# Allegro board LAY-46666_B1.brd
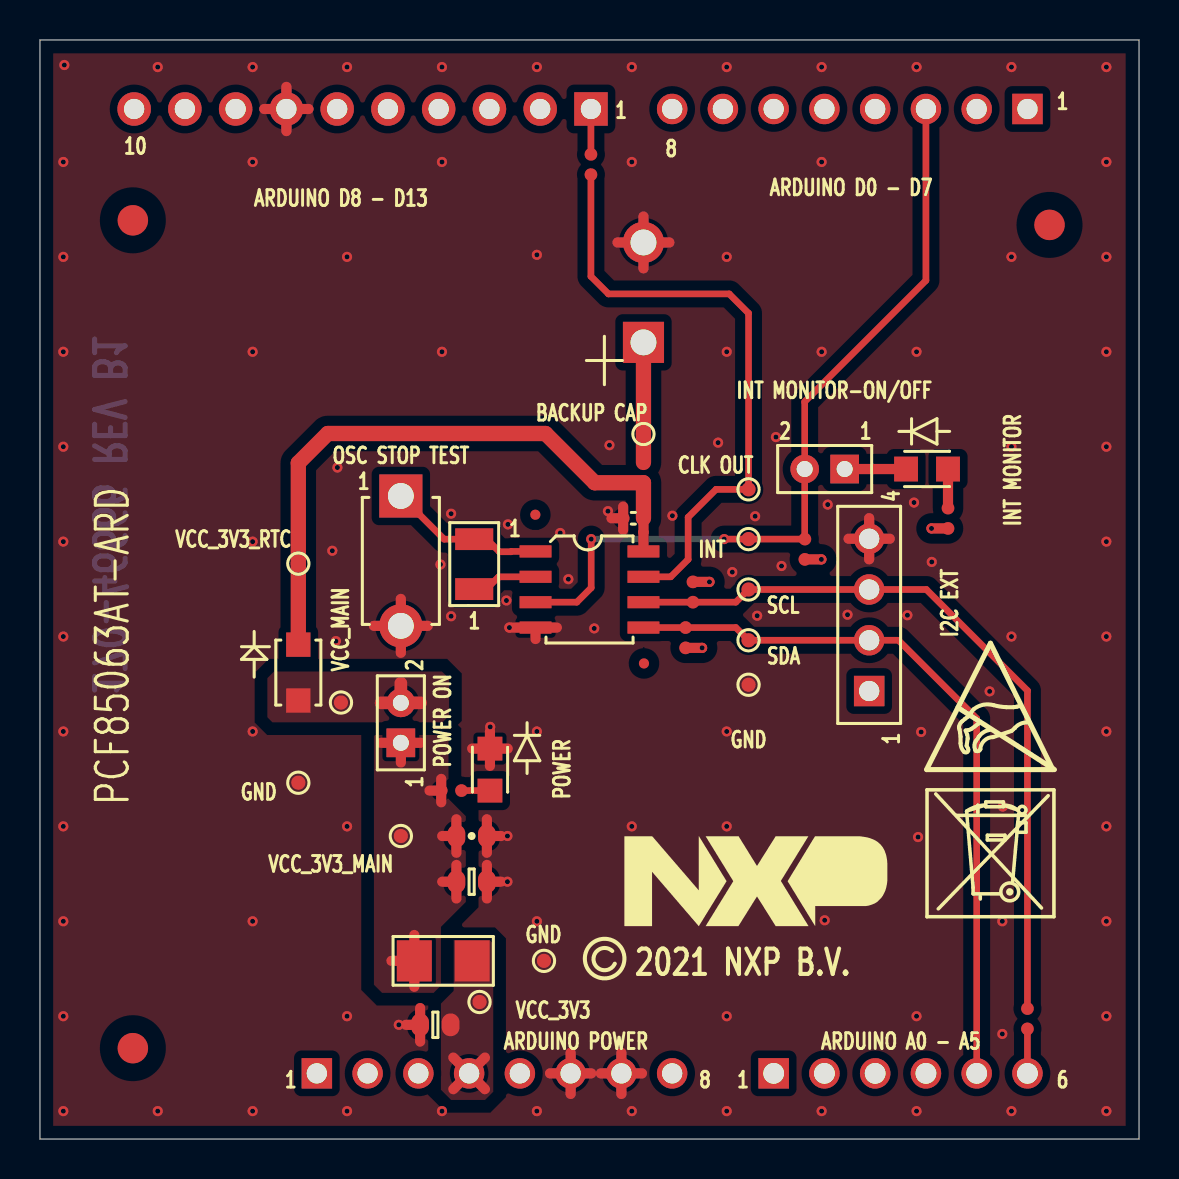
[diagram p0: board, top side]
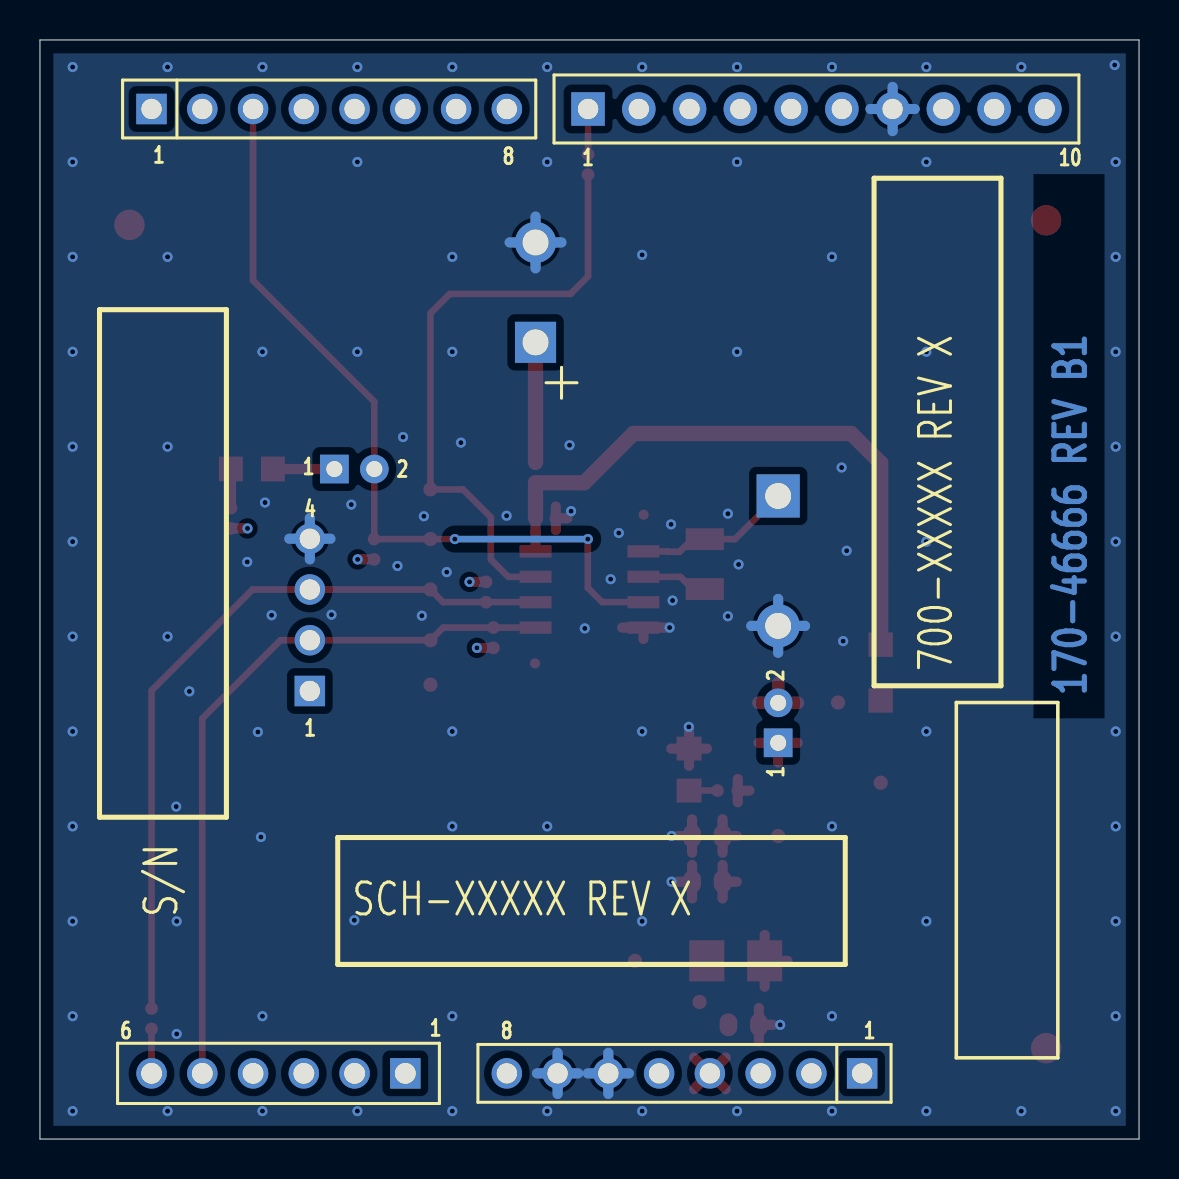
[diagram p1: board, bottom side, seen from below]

Outline 55 x 55 mm; copper layers: TOP, L2_GND, L3_PWR, BOTTOM. Coordinates in mm from the lower left corner of the outline.
Outline path: 0,55 0,0 55,0 55,55 0,55

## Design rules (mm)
constraint set DEFAULT: min track width 0.33
net group POWER: nets VCC_3V3_RTC

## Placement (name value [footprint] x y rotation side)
C1  10uF  [CC0603_OV]  19.79 5.71 180 top
C3  10uF  [CC0603_OV]  21.6 12.88 0 top
C7  0.1uF  [CC0402_25]  29.69 31.06 180 top
C8  1F  [CAP_5X19P2_TH]  30.2 42.37 270 top
D1  RED  [LED_2P_0805]  22.52 18.49 270 top
D2  RED  [LED_2P_0805]  44.39 33.53 0 top
D3  BAT54H,115  [SOD123W]  12.93 23.34 270 top
J1  HDR 1X6  [HDR106_TH_TSW]  36.72 3.29 270 bottom
J4  TSW-110-07-T-S  [HDR110]  27.57 51.55 90 bottom
J5  TSW-108-07-T-S  [JUMP1X8-6040]  49.42 51.55 90 bottom
J6  TSW-108-07-T-S  [JUMP1X8-6040]  13.86 3.29 270 bottom
J24  HDR 1x2 TH  [HDR102_78MIL_TH]  40.27 33.53 0 top
J37  HDR 1x2 TH  [HDR102_78MIL_TH]  18.06 19.83 270 top
J38  HDR_1X4  [HDR104_2P54_TH]  41.49 22.42 180 top
L2  100 OHM  [IND_1206A]  20.18 8.92 180 top
NOREF  -  []  25.81 28.43 90 top
NOREF#2  -  [unnamed#2]  30.23 23.8 0 top
NOREF#3  -  []  13.88 20.04 90 top
NOREF#4  -  []  29.26 10.66 0 top
NOREF#5  -  []  0 0 0 top
NOREF#6  -  []  42.89 10.46 0 top
NOREF#7  -  [unnamed#2]  4.65 4.55 0 top
NOREF#8  -  []  30.2 39.87 90 top
NOREF#9  -  []  28.26 9 0 top
NOREF#10  -  []  71.58 -68.17 0 top
NOREF#11  -  []  19.81 28.43 0 top
NOREF#12  -  []  38.27 33.53 0 top
NOREF#13  -  []  -313.23 -292.32 0 top
NOREF#14  -  []  41.49 22.42 90 top
NOREF#15  -  []  -286.56 228.76 0 top
NOREF#16  -  []  20.6 44.87 0 top
NOREF#17  -  []  45.68 10.46 90 top
NOREF#18  -  []  17.06 23 0 top
NOREF#19  -  []  44.39 18.49 0 top
NOREF#20  -  []  41.49 22.42 90 top
NOREF#21  -  [unnamed#2]  50.52 45.75 0 top
NOREF#22  -  []  0 0 0 top
NOREF#23  -  []  0 55 0 top
NOREF#24  -  []  44.39 11.13 0 top
NOREF#25  -  [unnamed#2]  4.65 45.97 0 top
NOREF#26  -  []  18.06 25.68 90 top
NOREF#27  -  []  55 0 90 top
NOREF#28  -  []  25.03 51.55 0 top
NOREF#29  -  []  11.08 20.04 0 top
NOREF#30  -  []  18.06 19.83 90 top
NOREF#31  -  []  2.16 10.67 0 top
NOREF#32  -  []  21.41 23 90 top
NOREF#33  -  []  0 0 0 top
NOREF#34  -  []  25.6 44.87 90 top
NOREF#35  -  []  41.44 32.53 90 top
NOREF#36  -  []  37.09 32.53 0 top
NOREF#37  -  [unnamed#2]  24.79 31.24 180 top
NOREF#38  -  []  45.67 16.1 90 bottom
NOREF#39  -  []  6.91 22.68 90 bottom
NOREF#40  -  []  40.1 8.74 180 bottom
NOREF#41  -  []  9.14 21.84 270 bottom
R1  330 OHM  [RC0402_25]  20.59 17.44 0 top
R2  5.6K  [RC0402_25]  38.28 29.51 90 top
R3  AVR-M1608C080MTAAB  [RC0603_OV]  21.6 15.16 0 top
R29  750  [RC0402_25]  45.44 31.06 90 top
R30  5.6K  [RC0402_25]  32.68 27.37 270 top
R31  5.6K  [RC0402_25]  32.31 25.09 90 top
R32  47  [RC0402_25]  30.2 33.35 270 top
R35  0  [RC0402_25]  27.57 48.77 90 top
R36  0  [RC0402_25]  49.42 6.02 270 top
SW1  TL1107  [SW2_6P5_6X3MM_TH]  18.06 32.18 270 top
TP1  -  [TPAD_028]  35.46 32.51 0 top
TP2  -  [TPAD_028]  35.46 30.02 0 top
TP3  -  [TPAD_028]  35.46 24.96 0 top
TP4  -  [TPAD_028]  35.46 27.5 0 top
TP5  -  [TPAD_028]  22 6.86 0 top
TP6  -  [TPAD_028]  30.2 35.28 0 top
TP7  -  [TPAD_028]  18.06 15.16 0 top
TP8  -  [TPAD_028]  12.93 28.8 0 top
TP9  -  [TPAD_028]  25.22 8.92 0 top
TP10  -  [TPAD_028]  12.93 17.83 0 top
TP11  -  [TPAD_028]  15.06 21.84 0 top
TP12  -  [TPAD_028]  35.46 22.73 0 top
U1  PCF85063AT/A  [SO8_1P27_4X5]  27.5 27.5 0 top
Y1  32.768kHz  [XTAL2-3P2X1P5-SM]  21.73 28.77 90 top

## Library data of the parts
C1 C3 C7 = CAP_NP
C8 = CAP_POL
D1 D2 = LED
D3 = DIODE_SCHTKY
J1 = CONN_HDR_6X1
J4 = CONN_HDR_10X1
J5 J6 = HDR-1X8
J24 J37 = HDR_1X2_TH
J38 = CONN_HDR_4X1
L2 = IND_BF: tolerance: XXXX
R1 R2 R29-R32 R35 R36 = RES
R3 = VARISTOR
SW1 = SW2P
TP1-TP12 = TESTLOOP
U1 = PCF85063ATT_A
Y1 = XTAL

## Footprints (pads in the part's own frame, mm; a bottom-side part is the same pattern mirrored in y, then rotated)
CAP_5X19P2_TH
  rect 2.057x2.057 hole 1.295: 1(2.5,0)
  round 2.057 hole 1.295: 2(-2.5,0)
CC0402_25
  round 0.635 smd: 1(-0.508,0) 2(0.508,0)
CC0603_OV
  oval 0.889x1.143 smd: 1(-0.762,0) 2(0.762,0)
HDR102_78MIL_TH
  rect 1.435x1.435 hole 0.8: 1(0,0)
  round 1.435 hole 0.8: 2(-2,0)
HDR104_2P54_TH
  rect 1.524x1.524 hole 1.016: 1(0,0)
  round 1.524 hole 1.016: 2(0,-2.54) 3(0,-5.08) 4(0,-7.62)
HDR106_TH_TSW
  rect 1.524x1.524 hole 1.041: 1(0,0)
  round 1.524 hole 1.041: 2(0,-2.54) 3(0,-5.08) 4(0,-7.62) 5(0,-10.16) 6(0,-12.7)
HDR110
  rect 1.676x1.676 hole 1.016: 1(0,0)
  round 1.676 hole 1.016: 2(0,-2.54) 3(0,-5.08) 4(0,-7.62) 5(0,-10.16) 6(0,-12.7) 7(0,-15.24) 8(0,-17.78) 9(0,-20.32) 10(0,-22.86)
IND_1206A
  rect 1.753x2.057 smd: 1(-1.448,0) 2(1.448,0)
JUMP1X8-6040
  rect 1.524x1.524 hole 1.016: 1(0,0)
  round 1.524 hole 1.016: 2(0,-2.54) 3(0,-5.08) 4(0,-7.62) 5(0,-10.16) 6(0,-12.7) 7(0,-15.24) 8(0,-17.78)
LED_2P_0805
  rect 1.194x1.245 smd: A(1.05,0) C(-1.05,0)
RC0402_25
  round 0.635 smd: 1(-0.508,0) 2(0.508,0)
RC0603_OV
  oval 0.889x1.143 smd: 1(-0.762,0) 2(0.762,0)
SO8_1P27_4X5
  rect 1.6x0.61 smd: 1(-2.7,1.905) 2(-2.7,0.635) 3(-2.7,-0.635) 4(-2.7,-1.905) 5(2.7,-1.905) 6(2.7,-0.635) 7(2.7,0.635) 8(2.7,1.905)
SOD123W
  rect 1.219x1.219 smd: A(1.4,0) C(-1.4,0)
SW2_6P5_6X3MM_TH
  rect 2.159x2.159 hole 1.295: 1(0,0)
  round 2.159 hole 1.295: 2(6.5,0)
TPAD_028
  round 0.711 smd: 1(0,0)
unnamed#2
  round 0.508 smd: (0,0)
XTAL2-3P2X1P5-SM
  rect 1.092x1.905 smd: 1(-1.25,0) 2(1.25,0)

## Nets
GND: C1.2 C3.2 C7.2 C8.2 D1.C(CATHODE) J4.7 J6.6 J6.7 J38.4 R3.2 SW1.2(NO) TP9.1(PIN1) TP10.1(PIN1) TP12.1(PIN1) U1.4(VSS)
VCC_3V3: C1.1 J6.4 J38.1 L2.1 TP5.1(PIN1)
VCC_3V3_MAIN: C3.1 J37.1 L2.2 R1.1 R3.1 TP7.1(PIN1)
VCC_3V3_RTC: C7.1 D3.C R32.2 TP8.1(PIN1) U1.8
VCC_MAIN: D3.A J37.2 R2.1 R29.1 R30.1 R31.1 TP11.1(PIN1)
CLK_OUT: J4.1 R35.2
I2C_3V3_SCL: J38.3 R30.2 R36.1 TP4.1(PIN1) U1.6
I2C_3V3_SDA: J1.5 J38.2 R31.2 TP3.1(PIN1) U1.5
I2C_SCL: J1.6 R36.2
INT_LED: D2.A R29.2
LED_3V3: D1.A R1.2
OSCI: SW1.1 U1.1 Y1.2
OSCO: U1.2 Y1.1
RTC_CLKOUT: R35.1 TP1.1(PIN1) U1.7
RTC_INT_B: J5.3 J24.2 R2.2 TP2.1(PIN1) U1.3
RTC_LED: D2.C(CATHODE) J24.1
SPR_CAP: C8.1 R32.1 TP6.1(PIN1)

Pads without a net: J1 1 2 3 4; J4 2 3 4 5 6 8 9 10; J5 1 2 4 5 6 7 8; J6 1 2 3 5 8

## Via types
v1: diameter 0.508, hole 0.254, TOP to BOTTOM, 114 vias

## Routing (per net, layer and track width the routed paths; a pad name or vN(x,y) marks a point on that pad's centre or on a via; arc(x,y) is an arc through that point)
GND: length 112.2
  TOP w0.508: J38.4 42.52,30.04 ; J38.4 41.49,29.01 ; J38.4 41.49,31.07 ; J38.4 40.47,30.04 ; 22.36,12.04 C3.2 ; C3.2 23.08,12.88 ; C3.2 22.36,13.72 ; J6.6 26.56,4.32 ; J6.6 27.59,3.29 ; J6.6 25.53,3.29 ; J6.6 26.56,2.26 ; C7.2 29.18,31.65 ; C7.2 29.18,30.48 ; C7.2 28.6,31.06 ; C8.2 31.5,44.87 ; C8.2 28.9,44.87 ; C8.2 30.2,46.16 ; C8.2 30.2,43.57 ; J6.7 29.1,4.32 ; J6.7 28.07,3.29 ; J6.7 29.1,2.26 ; J6.7 30.13,3.29 ; SW1.2 18.06,27.03 ; SW1.2 19.41,25.68 ; SW1.2 18.06,24.33 ; SW1.2 16.71,25.68 ; 21.63,19.54 D1.C ; D1.C 23.41,19.54 ; D1.C 22.52,20.4 ; D1.C 22.52,18.67 ; R3.2 23.08,15.16 ; R3.2 22.36,14.33 ; R3.2 22.36,16 ; U1.4 v1(23.49,25.59) ; U1.4 25.87,25.59 ; U1.4 24.8,25.02 ; 11.23,51.55 J4.7 ; J4.7 12.33,50.44 ; J4.7 12.33,52.65 ; J4.7 13.44,51.55 ; 18.31,5.71 C1.2 ; C1.2 19.02,6.55 ; C1.2 19.02,4.88
  L2_GND w0.508: 18.06,24.41 SW1.2 ; SW1.2 16.79,25.68 ; SW1.2 19.33,25.68 ; SW1.2 18.06,26.95 ; 29.1,2.33 J6.7 ; J6.7 29.1,4.24 ; J6.7 28.14,3.29 ; J6.7 30.05,3.29 ; J4.7 13.36,51.55 ; J4.7 11.3,51.55 ; J4.7 12.33,52.58 ; J4.7 12.33,50.52 ; J6.6 27.51,3.29 ; J6.6 26.56,4.24 ; J6.6 25.6,3.29 ; J6.6 26.56,2.33 ; 40.54,30.04 J38.4 ; J38.4 41.49,30.99 ; J38.4 42.45,30.04 ; J38.4 41.49,29.09 ; C8.2 30.2,46.09 ; C8.2 28.98,44.87 ; C8.2 31.42,44.87 ; C8.2 30.2,43.65
  L3_PWR w0.508: J4.7 12.33,52.58 ; J4.7 11.3,51.55 ; J4.7 13.36,51.55 ; J4.7 12.33,50.52 ; 29.1,2.33 J6.7 ; J6.7 28.14,3.29 ; J6.7 30.05,3.29 ; J6.7 29.1,4.24 ; 25.6,3.29 J6.6 ; J6.6 26.56,4.24 ; J6.6 26.56,2.33 ; J6.6 27.51,3.29 ; C8.2 31.42,44.87 ; C8.2 30.2,43.65 ; C8.2 28.98,44.87 ; C8.2 30.2,46.09
  BOTTOM w0.508: 18.06,24.33 SW1.2 ; SW1.2 16.71,25.68 ; SW1.2 19.41,25.68 ; SW1.2 18.06,27.03 ; J6.7 30.13,3.29 ; J6.7 29.1,2.26 ; J6.7 29.1,4.32 ; J6.7 28.07,3.29 ; 26.56,2.26 J6.6 ; J6.6 27.59,3.29 ; J6.6 26.56,4.32 ; J6.6 25.53,3.29 ; 40.47,30.04 J38.4 ; J38.4 42.52,30.04 ; J38.4 41.49,31.07 ; J38.4 41.49,29.01 ; 11.23,51.55 J4.7 ; J4.7 12.33,50.44 ; J4.7 12.33,52.65 ; J4.7 13.44,51.55 ; 28.9,44.87 C8.2 ; C8.2 30.2,46.16 ; C8.2 30.2,43.57 ; C8.2 31.5,44.87
  vias: v1(1.22,53.75) v1(1.17,48.9) v1(1.17,44.15) v1(1.17,39.4) v1(1.17,34.65) v1(1.17,29.9) v1(1.17,25.15) v1(1.17,20.4) v1(1.17,15.65) v1(1.17,10.9) v1(1.17,6.15) v1(1.17,1.4) v1(5.89,53.64) v1(5.89,1.4) v1(10.64,53.64) v1(10.64,48.9) v1(10.64,39.4) v1(10.64,29.9) v1(10.64,20.4) v1(10.64,10.9) v1(10.64,1.4) v1(14.63,29.44) v1(14.81,24.92) v1(14.88,33.6) v1(15.37,53.64) v1(15.37,44.15) v1(15.37,15.65) v1(15.37,6.15) v1(15.37,1.4) v1(17.96,5.71) v1(20.04,28.75) v1(20.12,53.64) v1(20.12,48.9) v1(20.12,39.4) v1(20.12,1.4) v1(20.57,31.29) v1(20.57,26.16) v1(22.53,20.62) v1(23.34,26.95) v1(23.42,30.76) v1(23.39,15.16) v1(23.39,12.88) v1(24.87,53.64) v1(24.87,44.25) v1(24.87,20.4) v1(24.87,10.9) v1(24.87,1.4) v1(26.04,30.33) v1(26.44,28.02) v1(27.74,25.55) v1(28.42,31.42) v1(28.5,34.72) v1(29.62,53.64) v1(29.62,48.9) v1(29.62,15.65) v1(29.62,1.4) v1(31.65,31.19) v1(33.93,34.85) v1(34.37,53.64) v1(34.37,44.15) v1(34.37,39.4) v1(34.37,20.4) v1(34.37,15.65) v1(34.37,6.15) v1(34.37,1.4) v1(34.65,28.37) v1(35.79,31.17) v1(35.89,26.19) v1(36.83,35.13) v1(37.11,28.68) v1(39.12,53.64) v1(39.12,48.9) v1(39.12,39.4) v1(39.12,1.4) v1(39.27,10.95) v1(39.42,31.75) v1(40.41,26.24) v1(43.41,26.21) v1(43.74,31.85) v1(43.87,53.64) v1(43.87,39.4) v1(43.94,15.11) v1(43.87,6.15) v1(43.87,1.4) v1(44.09,20.37) v1(44.63,28.88) v1(47.52,22.4) v1(48.18,16.64) v1(48.16,10.9) v1(48.16,5.26) v1(48.62,53.64) v1(48.62,44.15) v1(48.62,34.65) v1(48.62,25.15) v1(48.62,1.4) v1(53.37,53.64) v1(53.37,48.9) v1(53.37,44.15) v1(53.37,39.4) v1(53.37,34.65) v1(53.37,29.9) v1(53.37,25.15) v1(53.37,20.4) v1(53.37,15.65) v1(53.37,10.9) v1(53.37,6.15) v1(53.37,1.4)
VCC_3V3: length 12.8
  TOP w0.508: 20.68,4.08 J6.4 ; J6.4 20.68,2.49 ; J6.4 22.27,2.49 ; J6.4 22.27,4.08
  L3_PWR w0.508: 20.74,4.02 J6.4 ; J6.4 20.74,2.55 ; J6.4 22.21,2.55 ; J6.4 22.21,4.02 ; 40.76,21.68 J38.1 ; J38.1 42.23,23.16 ; J38.1 42.23,21.68 ; J38.1 40.76,23.16
VCC_3V3_MAIN: length 13.2
  TOP w0.508: 19.49,17.44 R1.1 ; R1.1 20.08,16.85 ; R1.1 20.08,18.02 ; 18.06,18.84 J37.1 ; J37.1 19.04,19.83 ; J37.1 17.07,19.83 ; 20.13,12.88 C3.1 ; C3.1 20.84,12.04 ; C3.1 20.84,13.72 ; 17.59,8.92 L2.2 ; L2.2 18.73,7.62 ; L2.2 18.73,10.21 ; 20.13,15.16 R3.1 ; R3.1 20.84,16 ; R3.1 20.84,14.33
VCC_3V3_RTC: length 31.4
  TOP w0.508: C7.1 30.2,30.37 U1.8
  TOP w0.762: C7.1 R32.2 27.76,32.84 25.3,35.31 14.4,35.31 12.93,33.83 TP8.1 D3.C
VCC_MAIN: length 9
  TOP w0.508: R29.1 v1(44.62,30.56) ; R30.1 v1(33.5,27.88) ; R2.1 v1(39.1,29.01) ; R31.1 v1(33.13,24.58)
  TOP w0.635: J37.2 19.04,21.83 ; J37.2 17.07,21.83 ; J37.2 18.06,22.81
  L3_PWR w0.889: J37.2 18.06,22.74 ; J37.2 18.97,21.83 ; J37.2 17.15,21.83
CLK_OUT: length 2.3
  TOP w0.33: J4.1 R35.2
I2C_3V3_SCL: length 37.5
  TOP w0.33: U1.6 R30.2 34.82,26.86 TP4.1 J38.3 44.36,27.5 49.42,22.44 R36.1
I2C_3V3_SDA: length 36.3
  TOP w0.33: U1.5 R31.2 34.82,25.59 TP3.1 J38.2 42.96,24.96 46.88,21.04 J1.5
I2C_SCL: length 2.2
  TOP w0.33: J1.6 R36.2
INT_LED: length 2
  TOP w0.508: R29.2 D2.A
LED_3V3: length 1.4
  TOP w0.33: R1.2 D1.A
OSCI: length 7.9
  TOP w0.33: SW1.1 20.22,30.02 Y1.2 22.35,30.02 22.99,29.39 23.57,29.39 23.59,29.4 U1.1
OSCO: length 3.3
  TOP w0.33: U1.2 22.95,28.13 22.34,27.52 Y1.1
RTC_CLKOUT: length 30.9
  TOP w0.33: U1.7 31.56,28.13 32.44,29.01 32.44,31.11 33.83,32.51 TP1.1 35.46,41.33 34.49,42.29 28.45,42.29 27.57,43.17 R35.1
RTC_INT_B: length 40.3
  TOP w0.33: v1(34.24,30.02) TP2.1 R2.2 38.27,30.03 J24.2 38.27,36.9 44.34,42.96 J5.3 ; U1.3 26.86,26.86 27.58,27.58 v1(27.58,30.02)
  BOTTOM w0.33: v1(27.58,30.02) v1(34.24,30.02)
RTC_LED: length 3.1
  TOP w0.508: D2.C J24.1
SPR_CAP: length 6
  TOP w0.762: C8.1 TP6.1 R32.1

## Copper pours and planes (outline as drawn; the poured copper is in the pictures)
GND on TOP: 0.66,54.33 54.33,54.33 54.33,0.66 0.66,0.66 ; 3 cut-outs
GND on BOTTOM, L2_GND, L3_PWR: 0.66,54.33 54.33,54.33 54.33,0.66 0.66,0.66
VCC_3V3 on TOP: 22.68,2.36 22.68,9.78 22.5,9.96 20.7,9.96 20.7,7.42 20.07,6.78 20.07,2.46 20.57,1.96 22.28,1.96
VCC_3V3 on L3_PWR: 22.86,2.79 22.86,4.01 24.92,6.07 33.02,6.07 43.15,16.21 43.15,22.76 42.47,23.44 40.11,23.44 28.55,11.89 21.74,11.89 20.09,10.24 20.09,2.77 20.7,2.16 22.23,2.16
VCC_3V3_MAIN on TOP: 20.35,17.93 20.35,17.12 21.31,16.15 21.31,11.86 20.07,10.62 20.07,7.65 19.74,7.32 17.12,7.32 16.71,7.72 16.71,20.17 17.12,20.57 20.17,20.57 20.45,20.29 20.45,18.03
VCC_MAIN on TOP: 20.14,20.85 20.47,21.18 20.47,23.04 20.12,23.39 11.71,23.39 11.38,23.06 11.38,21.11 11.63,20.85
VCC_MAIN on L3_PWR: 14.55,21.29 36.96,21.29 39.67,24 39.67,27.33 41.1,28.75 43.26,28.75 46.43,31.93 46.43,35.13 45.62,35.94 15.24,35.94 12.6,33.3 12.6,23.24

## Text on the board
BOTTOM: 07 | L4_SS | 170-46666 REV B1
Board Geometry/Soldermask Bottom: 08 | SECONDARY SOLDERMASK
Ref Des/Silkscreen Bottom: 09 | SECONDARY SILKSCREEN
User.Comments: 1 OF 1 | TEST PROBE | 1/1 | 1
TOP: 04 | L1_PS
Board Geometry/Soldermask Top: 03 | PRIMARY SOLDERMASK
Ref Des/Silkscreen Top: 02 | PRIMARY SILKSCREEN | PCF85063AT-ARD
L2_GND: 05 | L2_GND
L3_PWR: 06 | L3_PWR
XSECTION_CHART: *  SURFACE - AIR 0 MIL | *  DIELECTRIC - PISM_GREEN 0.4 MIL | L1 TOP CONDUCTOR - 1/2OZ_COPPER_PLATED 1.4 MIL | *  DIELECTRIC - FR-4 8 MIL | L2 L2_GND PLANE - 1OZ_COPPER 1.4 MIL | *  DIELECTRIC - FR-4 40 MIL | L3 L3_PWR PLANE - 1OZ_COPPER 1.4 MIL | L4 BOTTOM CONDUCTOR - 1/2OZ_COPPER_PLATED 1.4 MIL | DESIGN CROSS SECTION CHART | ___________________________ | TOTAL THICKNESS 62.4 MIL | 1-4
DIMENSION: LAYERS | L1 | L4 | TRACE WIDTH | SINGLE ENDED | 13 MIL | IMPEDANCE | 50 OHM | 8 | PRIMARY DATUM | GRID ORIGIN | 19 | 16 | IMPEDANCE REQUIREMENTS | IMPEDANCE TOLERANCE IS 10% | DETAIL | LAYER STACKUP | SCALE: NONE | BOARD THICKNESS TOLERANCE +/-10% | B | A
DISPLAY_TOP: 01 | PASTEMASK TOP
User.5: 10 | SECONDARY PASTEMASK
User.9: C | 5 | 3 | 1 | 2 | A | D | 10 | 8 | 4 | 6 | P8 | P1 | 19 | 20 | E | 16 | 14 | 13 | 9 | 25 | 32 | 24 | 17 | + | - | J | 12 | P | SILKSCREEN TOP
User.11: 2 | 8 | 1 | 7 | B1 | A1 | C | A | 5 | B18 | A18 | 13 | 9 | 100 | 99 | 19 | 20 | 2018 NXP B.V. | 10 | 14 | 3 | 39 | 40 | 6 | 4 | PCB EDGE | B12 | A12 | 37 | 48 | 36 | 25 | 24 | 12 | 16 | PCB EDGE SIDE | 11 | 6501 WILLIAM CANNON DRIVE WEST | AUSTIN. TEXAS 78735 USA | SHEET | THIS DOCUMENT CONTAINS INFORMATION | PROPRIETARY TO NXP AND SHALL NOT | BE USED FOR ENGINEERING DESIGN | PROCUREMENT OR MANUFACTURE IN WHOLE | OR IN PART WITHOUT THE CONSENT OF | NXP. | FILM | NAME | 19-02-19 | ___ COMPANY PUBLIC | ___ COMPANY INTERNAL | ___ COMPANY CONFIDENTIAL | NUMBER | 1 OF 14 | PRIMARY SIDE | X | 170-31407      REV C1 | 8MMINI-BB | NXP SEMICONDUCTORS
User.12: TP10 | TP11 | TP3 | TP4 | TP1 | 5 | 8 | 4 | 1 | VCC_3V3 | GND | VCC_MAIN | CLK OUT | TP7 | VCC_3V3_MAIN | VCC_5V0 | VCC_3V3_RTC | R3 | L2 | 2019 NXP B.V. | TP5 | C1 | J6 | C9 | C2 | R35 | R29 | C7 | TP9 | D3 | D2 | R2 | J5 | J35 | R32 | TP2 | 6 | 10 | J38 | D1 | J36 | 2 | SDA | SCL | U1 | C8 | INT | R34 | R33 | EXT_I2C | R1 | PWR_LED | C3 | J37 | TP6 | TP8 | R31 | R30 | Y1 | J24 | PCF85063TP-ARD | +
User.13: 1 | J6 | 8 | J5 | J35 | 6 | 4 | 10 | J36 | 2 | J37 | J24 | J38 | C8 | 170-46657 REV A | 700-XXXXX REV X | S/N | SCH-XXXXX REV X | +
User.21: OF 09
User.24: 22. THIS FAB_VIAFILL.ART SHOWS LOCATIONS OF VIA-IN-PAD TO BE FILLED. | 1/1 | 2
User.25: 24. | 1/1 | 3 | CAD DESIGNER: DELETE THIS FAB PAGE IF BACKDRILL IS NOT USED ON THIS DESIGN. | FAB SUPPLIER: DISREGARD THIS PAGE IF BACKDRILL REQUIRMENT IS NOT PROVIDED.
User.28: 01-22-21 | 02-02-21 | G.M. | B | B1 | SCHEMATICS UPDATE | PROCESS CORRECTION
User.32: TOP TO LAYER X | BACK DRILL REFERENCE | BOTTOM TO LAYER X | LAYER X | MUST CUT LAYER | LAYER X+1 | MUST NOT CUT LAYER | LAYER X-1
User.33: FIGURE | FINISHED_SIZE | 10.0 | 31.5 | 40.0 | 41.0 | 51.0 | DRILL CHART: TOP to BOTTOM | ALL UNITS ARE IN MILS | TOLERANCE_DRILL | +0.0/-10.0 | +2.0/-2.0 | +3.0/-3.0 | PLATED | QTY | 114 | 4 | 30 | 6
